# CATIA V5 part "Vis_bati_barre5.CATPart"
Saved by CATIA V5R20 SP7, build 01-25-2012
Part number: Vis_bati_barre5
Bounding box of the stored display mesh (mm): x -7 to 0.5, y 17.004 to 18.996, z -0.996 to 0.996
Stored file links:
  J:\IFMA\IAO\système avant mef\Vis_bati_barre5.CATPart
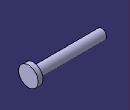
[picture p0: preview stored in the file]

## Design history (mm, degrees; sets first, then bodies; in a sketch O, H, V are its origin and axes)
Body1 (main body)
  Point1 "Point.Cprim": stored without definition
  Line1: stored without definition
  Plane1: type Normal, Curve Line1, RefPoint Point1
  Point2 "Point_F_vis": stored without definition
  Line2: stored without definition
  Line3 "axe_liaison_barre4_bati": stored without definition
  Line4 "axe_pivot_barre5_bati": stored without definition
  Sketch1 on Plane1, origin (0, 18, 0), H (-1, 0, 0), V (0, 0, 1)
    point P1 (7, 0)
    line L1 (7, 0) -> (7, 0.5)
    line L2 (7, 0.5) -> (0, 0.5)
    point P3 (0, 0.5)
    line L3 (0, 0.5) -> (0, 1)
    line L4 (0, 1) -> (-0.5, 1)
    line L5 (-0.5, 1) -> (-0.5, 0)
    point P6 (-0.5, 0)
    reference projected point E1 (7, 0) from Point2
    reference projected line E2 (9, 0) -> (2, 0) from Line2
    reference projected line E3 (0, 0) -> (-20, 0) from Line3
    distance L2 E2 = 0.5
    distance L5 L3 = 0.5
    distance L4 E3 = 1
    coincidence: P1 H, P3 V, P6 H, P1 E1
    vertical: L1 V, L3 V, L5 V
    horizontal: L2 H, L4 H
  Shaft1: profile Sketch1, axis Line4, angle 360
